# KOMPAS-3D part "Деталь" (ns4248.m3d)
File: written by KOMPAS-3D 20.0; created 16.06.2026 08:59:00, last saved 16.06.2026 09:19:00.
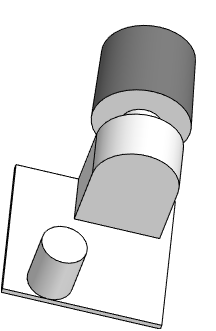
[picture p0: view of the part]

Document properties: Полное имя файла: D:\RicWork\Project-EPS32\box_compas\ns4248.m3d

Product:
- Part/product: Деталь
    Материал: Полипропилен  ГОСТ 26996-86 (density 900 kg/m3)
    Масса: 0.00646155
  - Body: Тело 1
      Масса: 0.0524533

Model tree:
1. Эскиз:1
2. Элемент выдавливания:1
     Расстояние 1 = 1
3. Эскиз:2  (with: Элемент выдавливания:1)
4. Элемент выдавливания:2
     Расстояние 1 = 20
5. Скругление:1  (with: Элемент выдавливания:2)
     Радиус = 7.5
6. Эскиз:3  (with: Элемент выдавливания:1, Элемент выдавливания:2)
7. Элемент выдавливания:3
     Расстояние 1 = 5
8. Эскиз:4  (with: Элемент выдавливания:3)
9. Элемент выдавливания:4
     Расстояние 1 = 15
10. Уклон:1  (with: Элемент выдавливания:4)
     Угол уклона = 2
11. Эскиз:7  (with: Элемент выдавливания:1)
12. Элемент выдавливания:5  (labels: Полипропилен  ГОСТ 26996-86)
     Расстояние 1 = 10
